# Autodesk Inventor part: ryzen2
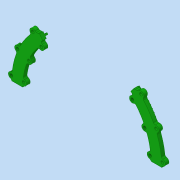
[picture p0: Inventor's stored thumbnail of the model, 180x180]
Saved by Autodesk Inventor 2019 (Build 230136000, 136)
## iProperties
Created: 2022-03
Part Number: ryzen2
Material: Типовые
Document SubType Name: Modeling
Designer: mitof
Density: 1 g/cm^3
Appearance: Темно-зеленый
Author: mitof
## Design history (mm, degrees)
sketch "Эскиз1"
  geometry: L1 (-74.2, 0)-(-71, 0); L2 (-83, 0)-(-79.8, 0); L3 (57.032, 53.211)-(58.347, 54.439); L4 (55.732, 60)-(53.666, 60); L5 (-53.666, 60)-(-55.732, 60); L6 (79.8, 0)-(83, 0); L7 (71, 0)-(74.2, 0); L8 (-58.347, 54.439)-(-57.032, 53.211); L9 (-55.57, 51.846)-(-54.254, 50.617); L10 (54.254, 50.617)-(55.57, 51.846); L11 (-79.8, 0)-(-74.2, 0); L12 (74.2, 0)-(79.8, 0); C1 r 1.35 at (0, 81); C2 r 1.35 at (-83.5, 5); C3 r 1.35 at (-70, 5); C4 r 1.35 at (76.568, 33.925); C5 r 1.35 at (64.068, 28.64); C6 r 1.35 at (0, 73); C7 r 1.35 at (83.5, 5); C8 r 1.35 at (70, 5); C9 r 1.35 at (59.809, 58.536); C10 r 1.35 at (-59.809, 58.536); C11 r 1.35 at (-50.409, 48.825); C12 r 1.35 at (50.409, 48.825); C13 r 1.35 at (-76.568, 33.925); C14 r 1.35 at (-64.068, 28.64); A1 r 2 centre (-5.285, 81.829) between (-5.156, 79.834) and (-3.309, 81.519); A2 r 2 centre (5.285, 81.829) between (3.309, 81.519) and (5.156, 79.834); A3 r 3.35 centre (0, 81) between (3.309, 81.519) and (-3.309, 81.519); A4 r 2 centre (-84.376, 10.278) between (-84.049, 8.305) and (-82.391, 10.036); A5 r 3.35 centre (-83.5, 5) between (-84.049, 8.305) and (-84.436, 1.784); A6 r 2 centre (-68.263, 10.06) between (-70.241, 10.352) and (-68.912, 8.168); A7 r 3.35 centre (-70, 5) between (-69.384, 1.707) and (-68.912, 8.168); A8 r 2 centre (-69.017, -0.259) between (-69.384, 1.707) and (-71, 0); A9 r 2 centre (-84.995, -0.137) between (-83, 0) and (-84.436, 1.784); A10 r 79.8 centre (0, 0) between (79.8, 0) and (58.347, 54.439); A11 r 71 centre (0, 0) between (70.241, 10.352) and (66.808, 24.036); A12 r 83 centre (0, 0) between (82.391, 10.036) and (77.812, 28.883); A13 r 74.2 centre (0, 0) between (74.2, 0) and (54.254, 50.617); A14 r 2 centre (64.926, 23.359) between (66.808, 24.036) and (64.605, 25.333); A15 r 2 centre (79.687, 29.579) between (78.521, 31.204) and (77.812, 28.883); A16 r 3.35 centre (76.568, 33.925) between (78.521, 31.204) and (75.864, 37.201); A17 r 3.35 centre (64.068, 28.64) between (61.962, 31.245) and (64.605, 25.333); A18 r 2 centre (75.444, 39.156) between (73.669, 38.235) and (75.864, 37.201); A19 r 83 centre (0, 0) between (73.669, 38.235) and (62.774, 54.299); A20 r 2 centre (-5.216, 71.811) between (-3.266, 72.255) and (-5.361, 73.806); A21 r 3.35 centre (0, 73) between (-3.266, 72.255) and (3.266, 72.255); A22 r 80 centre (0, 0) between (52.357, 60.488) and (5.156, 79.834); A23 r 80 centre (0, 0) between (-5.156, 79.834) and (-52.357, 60.488); A24 r 74 centre (0, 0) between (-5.361, 73.806) and (-49.753, 54.778); A25 r 2 centre (53.666, 62) between (52.357, 60.488) and (53.666, 60); A26 r 2 centre (-53.666, 62) between (-53.666, 60) and (-52.357, 60.488); A27 r 78 centre (0, 0) between (57.032, 53.211) and (-57.032, 53.211); A28 r 76 centre (0, 0) between (55.57, 51.846) and (-55.57, 51.846); A29 r 2 centre (84.995, -0.137) between (84.436, 1.784) and (83, 0); A30 r 2 centre (68.263, 10.06) between (68.912, 8.168) and (70.241, 10.352); A31 r 3.35 centre (70, 5) between (68.912, 8.168) and (69.384, 1.707); A32 r 2 centre (84.376, 10.278) between (82.391, 10.036) and (84.049, 8.305); A33 r 2 centre (69.017, -0.259) between (71, 0) and (69.384, 1.707); A34 r 3.35 centre (83.5, 5) between (84.436, 1.784) and (84.049, 8.305); A35 r 2 centre (64.287, 55.608) between (62.613, 56.702) and (62.774, 54.299); A36 r 3.35 centre (59.809, 58.536) between (62.613, 56.702) and (57.256, 60.705); A37 r 2 centre (55.732, 62) between (55.732, 60) and (57.256, 60.705); A38 r 2 centre (-55.732, 62) between (-57.256, 60.705) and (-55.732, 60); A39 r 3.35 centre (-59.809, 58.536) between (-57.256, 60.705) and (-62.613, 56.702); A40 r 2 centre (-64.287, 55.608) between (-62.774, 54.299) and (-62.613, 56.702); A41 r 2 centre (-48.408, 53.298) between (-49.753, 54.778) and (-50.393, 53.542); A42 r 2 centre (-48.408, 53.787) between (-50.393, 53.542) and (-49.156, 51.932); A43 r 3.35 centre (-50.409, 48.825) between (-52.045, 45.902) and (-49.156, 51.932); A44 r 2 centre (-53.021, 44.156) between (-52.045, 45.902) and (-54.558, 45.436); A45 r 2 centre (60.705, 32.801) between (61.962, 31.245) and (62.465, 33.751); A46 r 71 centre (0, 0) between (62.465, 33.751) and (54.558, 45.436); A47 r 2 centre (53.021, 44.156) between (54.558, 45.436) and (52.045, 45.902); A48 r 3.35 centre (50.409, 48.825) between (49.156, 51.932) and (52.045, 45.902); A49 r 2 centre (48.408, 53.787) between (49.156, 51.932) and (50.393, 53.542); A50 r 2 centre (48.408, 53.298) between (50.393, 53.542) and (49.753, 54.778); A51 r 74 centre (0, 0) between (49.753, 54.778) and (5.361, 73.806); A52 r 2 centre (5.216, 71.811) between (5.361, 73.806) and (3.266, 72.255); A53 r 83 centre (0, 0) between (-62.774, 54.299) and (-73.669, 38.235); A54 r 2 centre (-75.444, 39.156) between (-75.864, 37.201) and (-73.669, 38.235); A55 r 3.35 centre (-76.568, 33.925) between (-75.864, 37.201) and (-78.521, 31.204); A56 r 2 centre (-79.687, 29.579) between (-77.812, 28.883) and (-78.521, 31.204); A57 r 83 centre (0, 0) between (-77.812, 28.883) and (-82.391, 10.036); A58 r 71 centre (0, 0) between (-66.808, 24.036) and (-70.241, 10.352); A59 r 79.8 centre (0, 0) between (-58.347, 54.439) and (-79.8, 0); A60 r 74.2 centre (0, 0) between (-54.254, 50.617) and (-74.2, 0); A61 r 3.35 centre (-64.068, 28.64) between (-64.605, 25.333) and (-61.962, 31.245); A62 r 2 centre (-60.705, 32.801) between (-62.465, 33.751) and (-61.962, 31.245); A63 r 71 centre (0, 0) between (-54.558, 45.436) and (-62.465, 33.751); A64 r 2 centre (-64.926, 23.359) between (-64.605, 25.333) and (-66.808, 24.036); 2 further points
  constraints: 128 point on circle, 78 centre point, 24 end point, 2 collinear
extrude "Выдавливание1" new body sketch "Эскиз1" distance "d0" = 4; taper "d1" = 0 deg
sketch "Эскиз2"
  geometry: L1 (58.347, 54.439)-(57.032, 53.211) reference; L2 (55.57, 51.846)-(54.254, 50.617) reference; L3 (-57.032, 53.211)-(-58.347, 54.439) reference; L4 (-54.254, 50.617)-(-55.57, 51.846) reference; L5 (-54.537, 50.607)-(-55.852, 51.836); L6 (55.852, 51.836)-(54.537, 50.607); L7 (-58.337, 54.156)-(-57.022, 52.928); L8 (57.022, 52.928)-(58.337, 54.156); L9 (79.6, 0)-(74.4, 0); L10 (83, 0)-(71, 0) reference; L11 (-74.4, 0)-(-79.6, 0); L12 (-71, 0)-(-83, 0) reference; A1 r 74.2 centre (0, 0) between (74.2, 0) and (54.254, 50.617) reference; A2 r 79.8 centre (0, 0) between (79.8, 0) and (58.347, 54.439) reference; A3 r 78 centre (0, 0) between (57.032, 53.211) and (-57.032, 53.211) reference; A4 r 76 centre (0, 0) between (55.57, 51.846) and (-55.57, 51.846) reference; A5 r 74.2 centre (0, 0) between (-54.254, 50.617) and (-74.2, 0) reference; A6 r 79.8 centre (0, 0) between (-58.347, 54.439) and (-79.8, 0) reference; A7 r 74.4 centre (0, 0) between (-54.537, 50.607) and (-74.4, 0); A8 r 76.2 centre (0, 0) between (55.852, 51.836) and (-55.852, 51.836); A9 r 74.4 centre (0, 0) between (74.4, 0) and (54.537, 50.607); A10 r 79.6 centre (0, 0) between (-58.337, 54.156) and (-79.6, 0); A11 r 77.8 centre (0, 0) between (57.022, 52.928) and (-57.022, 52.928); A12 r 79.6 centre (0, 0) between (79.6, 0) and (58.337, 54.156); 1 further point
  constraints: 12 end point, 12 point on circle, 6 centre point, 1 collinear, 8 other
  dimensions: "d2" = 0.2 radial gap between concentric circles of A5 A7; "d3" = 0.2 radial gap between concentric circles of A6 A10
extrude "Выдавливание2" join sketch "Эскиз2" distance "d4" = 3; taper "d5" = 0 deg
sketch "Эскиз3"
  geometry: L1 (71, 0)-(83, 0) reference; L2 (55.732, 60)-(53.666, 60) reference; L3 (-53.666, 60)-(-55.732, 60) reference; L4 (-83, 0)-(-71, 0) reference; C1 r 1.35 at (-83.5, 5) reference; C2 r 1.6 at (-83.5, 5); C3 r 1.35 at (-76.568, 33.925) reference; C4 r 1.35 at (-59.809, 58.536) reference; C5 r 1.35 at (59.809, 58.536) reference; C6 r 1.35 at (83.5, 5) reference; C7 r 1.35 at (76.568, 33.925) reference; C8 r 1.35 at (-83.5, 5) reference; C9 r 1.35 at (0, 81) reference; C10 r 1.35 at (-64.068, 28.64) reference; C11 r 1.35 at (50.409, 48.825) reference; C12 r 1.35 at (-50.409, 48.825) reference; C13 r 1.35 at (70, 5) reference; C14 r 1.35 at (0, 73) reference; C15 r 1.35 at (64.068, 28.64) reference; C16 r 1.35 at (-70, 5) reference; C17 r 1.6 at (-70, 5); C18 r 1.6 at (-76.568, 33.925); C19 r 1.6 at (-64.068, 28.64); C20 r 1.6 at (-59.809, 58.536); C21 r 1.6 at (-50.409, 48.825); C22 r 1.6 at (0, 73); C23 r 1.35 at (0, 81) reference; C24 r 1.6 at (0, 81); C25 r 1.6 at (50.409, 48.825); C26 r 1.6 at (59.809, 58.536); C27 r 1.6 at (64.068, 28.64); C28 r 1.6 at (76.568, 33.925); C29 r 1.6 at (70, 5); C30 r 1.6 at (83.5, 5); A1 r 71 centre (0, 0) between (-66.808, 24.036) and (-70.241, 10.352) reference; A2 r 2 centre (-64.926, 23.359) between (-64.605, 25.333) and (-66.808, 24.036) reference; A3 r 3.35 centre (-64.068, 28.64) between (-64.605, 25.333) and (-61.962, 31.245) reference; A4 r 2 centre (-60.705, 32.801) between (-62.465, 33.751) and (-61.962, 31.245) reference; A5 r 71 centre (0, 0) between (-54.558, 45.436) and (-62.465, 33.751) reference; A6 r 2 centre (-53.021, 44.156) between (-52.045, 45.902) and (-54.558, 45.436) reference; A7 r 3.35 centre (-50.409, 48.825) between (-52.045, 45.902) and (-49.156, 51.932) reference; A8 r 2 centre (-48.408, 53.787) between (-50.393, 53.542) and (-49.156, 51.932) reference; A9 r 2 centre (-48.408, 53.298) between (-49.753, 54.778) and (-50.393, 53.542) reference; A10 r 74 centre (0, 0) between (-5.361, 73.806) and (-49.753, 54.778) reference; A11 r 2 centre (-5.216, 71.811) between (-3.266, 72.255) and (-5.361, 73.806) reference; A12 r 3.35 centre (0, 73) between (-3.266, 72.255) and (3.266, 72.255) reference; A13 r 2 centre (5.216, 71.811) between (5.361, 73.806) and (3.266, 72.255) reference; A14 r 74 centre (0, 0) between (49.753, 54.778) and (5.361, 73.806) reference; A15 r 2 centre (48.408, 53.298) between (50.393, 53.542) and (49.753, 54.778) reference; A16 r 2 centre (48.408, 53.787) between (49.156, 51.932) and (50.393, 53.542) reference; A17 r 3.35 centre (50.409, 48.825) between (49.156, 51.932) and (52.045, 45.902) reference; A18 r 2 centre (53.021, 44.156) between (54.558, 45.436) and (52.045, 45.902) reference; A19 r 71 centre (0, 0) between (62.465, 33.751) and (54.558, 45.436) reference; A20 r 2 centre (60.705, 32.801) between (61.962, 31.245) and (62.465, 33.751) reference; A21 r 3.35 centre (64.068, 28.64) between (61.962, 31.245) and (64.605, 25.333) reference; A22 r 2 centre (64.926, 23.359) between (66.808, 24.036) and (64.605, 25.333) reference; A23 r 71 centre (0, 0) between (70.241, 10.352) and (66.808, 24.036) reference; A24 r 2 centre (68.263, 10.06) between (68.912, 8.168) and (70.241, 10.352) reference; A25 r 3.35 centre (70, 5) between (68.912, 8.168) and (69.384, 1.707) reference; A26 r 2 centre (69.017, -0.259) between (71, 0) and (69.384, 1.707) reference; A27 r 2 centre (84.995, -0.137) between (84.436, 1.784) and (83, 0) reference; A28 r 3.35 centre (83.5, 5) between (84.436, 1.784) and (84.049, 8.305) reference; A29 r 2 centre (84.376, 10.278) between (82.391, 10.036) and (84.049, 8.305) reference; A30 r 83 centre (0, 0) between (82.391, 10.036) and (77.812, 28.883) reference; A31 r 2 centre (79.687, 29.579) between (78.521, 31.204) and (77.812, 28.883) reference; A32 r 3.35 centre (76.568, 33.925) between (78.521, 31.204) and (75.864, 37.201) reference; A33 r 2 centre (75.444, 39.156) between (73.669, 38.235) and (75.864, 37.201) reference; A34 r 83 centre (0, 0) between (73.669, 38.235) and (62.774, 54.299) reference; A35 r 2 centre (64.287, 55.608) between (62.613, 56.702) and (62.774, 54.299) reference; A36 r 3.35 centre (59.809, 58.536) between (62.613, 56.702) and (57.256, 60.705) reference; A37 r 2 centre (55.732, 62) between (55.732, 60) and (57.256, 60.705) reference; A38 r 2 centre (53.666, 62) between (52.357, 60.488) and (53.666, 60) reference; A39 r 80 centre (0, 0) between (52.357, 60.488) and (5.156, 79.834) reference; A40 r 2 centre (5.285, 81.829) between (3.309, 81.519) and (5.156, 79.834) reference; A41 r 3.35 centre (0, 81) between (3.309, 81.519) and (-3.309, 81.519) reference; A42 r 2 centre (-5.285, 81.829) between (-5.156, 79.834) and (-3.309, 81.519) reference; A43 r 80 centre (0, 0) between (-5.156, 79.834) and (-52.357, 60.488) reference; A44 r 2 centre (-53.666, 62) between (-53.666, 60) and (-52.357, 60.488) reference; A45 r 2 centre (-55.732, 62) between (-57.256, 60.705) and (-55.732, 60) reference; A46 r 3.35 centre (-59.809, 58.536) between (-57.256, 60.705) and (-62.613, 56.702) reference; A47 r 2 centre (-64.287, 55.608) between (-62.774, 54.299) and (-62.613, 56.702) reference; A48 r 83 centre (0, 0) between (-62.774, 54.299) and (-73.669, 38.235) reference; A49 r 2 centre (-75.444, 39.156) between (-75.864, 37.201) and (-73.669, 38.235) reference; A50 r 3.35 centre (-76.568, 33.925) between (-75.864, 37.201) and (-78.521, 31.204) reference; A51 r 2 centre (-79.687, 29.579) between (-77.812, 28.883) and (-78.521, 31.204) reference; A52 r 83 centre (0, 0) between (-77.812, 28.883) and (-82.391, 10.036) reference; A53 r 2 centre (-84.376, 10.278) between (-84.049, 8.305) and (-82.391, 10.036) reference; A54 r 3.35 centre (-83.5, 5) between (-84.049, 8.305) and (-84.436, 1.784) reference; A55 r 2 centre (-84.995, -0.137) between (-83, 0) and (-84.436, 1.784) reference; A56 r 2 centre (-69.017, -0.259) between (-69.384, 1.707) and (-71, 0) reference; A57 r 3.35 centre (-70, 5) between (-69.384, 1.707) and (-68.912, 8.168) reference; A58 r 2 centre (-68.263, 10.06) between (-70.241, 10.352) and (-68.912, 8.168) reference; A59 r 3.35 centre (0, 73) between (-3.266, 72.255) and (3.266, 72.255) reference; 1 further point
  constraints: 14 centre point, 14 coincident
  dimensions: "d6" = 3.2 diameter of C2; "d7" = 3.2 diameter of C17; "d8" = 3.2 diameter of C18; "d9" = 3.2 diameter of C19; "d10" = 3.2 diameter of C20; "d11" = 3.2 diameter of C21; "d12" = 3.2 diameter of C22; "d13" = 3.2 diameter of C24; "d14" = 3.2 diameter of C25; "d15" = 3.2 diameter of C26; "d16" = 3.2 diameter of C27; "d17" = 3.2 diameter of C28; "d18" = 3.2 diameter of C29; "d19" = 3.2 diameter of C30
extrude "Выдавливание3" cut sketch "Эскиз3" extent not by distance; stored distance "d20" = 2.2; taper "d21" = 0 deg
sketch "Эскиз4"
  geometry: L1 (-54.537, 50.607)-(-55.852, 51.836) reference; L2 (55.852, 51.836)-(54.537, 50.607) reference; L3 (74.4, 0)-(79.6, 0) reference; L4 (58.337, 54.156)-(57.022, 52.928) reference; L5 (-57.022, 52.928)-(-58.337, 54.156) reference; L6 (-79.6, 0)-(-74.4, 0) reference; L7 (56.089, 48.881)-(60.009, 52.297); L8 (57.761, 46.894)-(61.798, 50.171); A1 r 74.4 centre (0, 0) between (-54.537, 50.607) and (-74.4, 0) reference; A2 r 76.2 centre (0, 0) between (55.852, 51.836) and (-55.852, 51.836) reference; A3 r 74.4 centre (0, 0) between (74.4, 0) and (54.537, 50.607) reference; A4 r 79.6 centre (0, 0) between (79.6, 0) and (58.337, 54.156) reference; A5 r 77.8 centre (0, 0) between (57.022, 52.928) and (-57.022, 52.928) reference; A6 r 79.6 centre (0, 0) between (-58.337, 54.156) and (-79.6, 0) reference; A7 r 79.6 centre (0, 0) between (79.6, 0) and (58.337, 54.156) reference; 1 further point
  constraints: 4 end point, 4 point on circle
  dimensions: "d26" = 2 deg angle of L7 L8
extrude "Выдавливание4" cut sketch "Эскиз4" distance "d27" = 1.2; taper "d28" = 0 deg
fillet "Сопряжение1" dims "d29" = 1.2
pattern_circular "Круговой массив1" dims angle "d31" = 37 deg
mirror "Зеркальное отражение1"
sketch "Эскиз5"
  geometry: L1 (54.537, 50.607)-(55.852, 51.836) reference; L2 (-55.852, 51.836)-(-54.537, 50.607) reference; L3 (-71, 0)-(-74.4, 0) reference; L4 (74.4, 0)-(71, 0) reference; L5 (83, 0)-(79.6, 0) reference; L6 (53.666, 60)-(55.732, 60) reference; L7 (-55.732, 60)-(-53.666, 60) reference; L8 (-79.6, 0)-(-83, 0) reference; L9 (-58.337, 54.156)-(-57.022, 52.928) reference; L10 (57.022, 52.928)-(58.337, 54.156) reference; L11 (-55.1, 50.586)-(-56.416, 51.815); L12 (56.416, 51.815)-(55.1, 50.586); L13 (74.799, -0.4)-(70.611, -0.4); L14 (-70.611, -0.4)-(-74.799, -0.4); L15 (-79.199, -0.4)-(-83.417, -0.4); L16 (-55.732, 60.4)-(-53.666, 60.4); L17 (53.666, 60.4)-(55.732, 60.4); L18 (83.417, -0.4)-(79.199, -0.4); L19 (58.316, 53.59)-(57.001, 52.361); L20 (-57.001, 52.361)-(-58.316, 53.59); L21 (-58.316, 53.59)-(-58.045, 53.883); L22 (-57.022, 52.928)-(-58.337, 54.156) reference; L23 (-55.1, 50.586)-(-54.827, 50.879); L24 (-74.8, 0)-(-74.4, 0); L25 (-71, 0)-(-83, 0) reference; L26 (-79.2, 0)-(-79.6, 0); C1 r 1.6 at (-70, 5) reference; C2 r 1.6 at (-64.068, 28.64) reference; C3 r 1.6 at (-50.409, 48.825) reference; C4 r 1.6 at (0, 73) reference; C5 r 1.6 at (70, 5) reference; C6 r 1.6 at (64.068, 28.64) reference; C7 r 1.6 at (50.409, 48.825) reference; C8 r 1.6 at (59.809, 58.536) reference; C9 r 1.6 at (76.568, 33.925) reference; C10 r 1.6 at (83.5, 5) reference; C11 r 1.6 at (0, 81) reference; C12 r 1.6 at (-59.809, 58.536) reference; C13 r 1.6 at (-76.568, 33.925) reference; C14 r 1.6 at (-83.5, 5) reference; A1 r 74.4 centre (0, 0) between (74.4, 0) and (54.537, 50.607) reference; A2 r 76.2 centre (0, 0) between (55.852, 51.836) and (-55.852, 51.836) reference; A3 r 74.4 centre (0, 0) between (-54.537, 50.607) and (-74.4, 0) reference; A4 r 2 centre (-69.017, -0.259) between (-69.384, 1.707) and (-71, 0) reference; A5 r 3.35 centre (-70, 5) between (-69.384, 1.707) and (-68.912, 8.168) reference; A6 r 2 centre (-68.263, 10.06) between (-70.241, 10.352) and (-68.912, 8.168) reference; A7 r 71 centre (0, 0) between (-66.808, 24.036) and (-70.241, 10.352) reference; A8 r 2 centre (-64.926, 23.359) between (-64.605, 25.333) and (-66.808, 24.036) reference; A9 r 3.35 centre (-64.068, 28.64) between (-64.605, 25.333) and (-61.962, 31.245) reference; A10 r 2 centre (-60.705, 32.801) between (-62.465, 33.751) and (-61.962, 31.245) reference; A11 r 71 centre (0, 0) between (-54.558, 45.436) and (-62.465, 33.751) reference; A12 r 2 centre (-53.021, 44.156) between (-52.045, 45.902) and (-54.558, 45.436) reference; A13 r 3.35 centre (-50.409, 48.825) between (-52.045, 45.902) and (-49.156, 51.932) reference; A14 r 2 centre (-48.408, 53.787) between (-50.393, 53.542) and (-49.156, 51.932) reference; A15 r 2 centre (-48.408, 53.298) between (-49.753, 54.778) and (-50.393, 53.542) reference; A16 r 74 centre (0, 0) between (-5.361, 73.806) and (-49.753, 54.778) reference; A17 r 2 centre (-5.216, 71.811) between (-3.266, 72.255) and (-5.361, 73.806) reference; A18 r 3.35 centre (0, 73) between (-3.266, 72.255) and (3.266, 72.255) reference; A19 r 2 centre (5.216, 71.811) between (5.361, 73.806) and (3.266, 72.255) reference; A20 r 74 centre (0, 0) between (49.753, 54.778) and (5.361, 73.806) reference; A21 r 2 centre (48.408, 53.298) between (50.393, 53.542) and (49.753, 54.778) reference; A22 r 2 centre (48.408, 53.787) between (49.156, 51.932) and (50.393, 53.542) reference; A23 r 3.35 centre (50.409, 48.825) between (49.156, 51.932) and (52.045, 45.902) reference; A24 r 2 centre (53.021, 44.156) between (54.558, 45.436) and (52.045, 45.902) reference; A25 r 71 centre (0, 0) between (62.465, 33.751) and (54.558, 45.436) reference; A26 r 2 centre (60.705, 32.801) between (61.962, 31.245) and (62.465, 33.751) reference; A27 r 3.35 centre (64.068, 28.64) between (61.962, 31.245) and (64.605, 25.333) reference; A28 r 2 centre (64.926, 23.359) between (66.808, 24.036) and (64.605, 25.333) reference; A29 r 71 centre (0, 0) between (70.241, 10.352) and (66.808, 24.036) reference; A30 r 2 centre (68.263, 10.06) between (68.912, 8.168) and (70.241, 10.352) reference; A31 r 3.35 centre (70, 5) between (68.912, 8.168) and (69.384, 1.707) reference; A32 r 2 centre (69.017, -0.259) between (71, 0) and (69.384, 1.707) reference; A33 r 79.6 centre (0, 0) between (79.6, 0) and (58.337, 54.156) reference; A34 r 2 centre (84.995, -0.137) between (84.436, 1.784) and (83, 0) reference; A35 r 3.35 centre (83.5, 5) between (84.436, 1.784) and (84.049, 8.305) reference; A36 r 2 centre (84.376, 10.278) between (82.391, 10.036) and (84.049, 8.305) reference; A37 r 83 centre (0, 0) between (82.391, 10.036) and (77.812, 28.883) reference; A38 r 2 centre (79.687, 29.579) between (78.521, 31.204) and (77.812, 28.883) reference; A39 r 3.35 centre (76.568, 33.925) between (78.521, 31.204) and (75.864, 37.201) reference; A40 r 2 centre (75.444, 39.156) between (73.669, 38.235) and (75.864, 37.201) reference; A41 r 83 centre (0, 0) between (73.669, 38.235) and (62.774, 54.299) reference; A42 r 2 centre (64.287, 55.608) between (62.613, 56.702) and (62.774, 54.299) reference; A43 r 3.35 centre (59.809, 58.536) between (62.613, 56.702) and (57.256, 60.705) reference; A44 r 2 centre (55.732, 62) between (55.732, 60) and (57.256, 60.705) reference; A45 r 2 centre (53.666, 62) between (52.357, 60.488) and (53.666, 60) reference; A46 r 80 centre (0, 0) between (52.357, 60.488) and (5.156, 79.834) reference; A47 r 2 centre (5.285, 81.829) between (3.309, 81.519) and (5.156, 79.834) reference; A48 r 3.35 centre (0, 81) between (3.309, 81.519) and (-3.309, 81.519) reference; A49 r 2 centre (-5.285, 81.829) between (-5.156, 79.834) and (-3.309, 81.519) reference; A50 r 80 centre (0, 0) between (-5.156, 79.834) and (-52.357, 60.488) reference; A51 r 2 centre (-53.666, 62) between (-53.666, 60) and (-52.357, 60.488) reference; A52 r 2 centre (-55.732, 62) between (-57.256, 60.705) and (-55.732, 60) reference; A53 r 3.35 centre (-59.809, 58.536) between (-57.256, 60.705) and (-62.613, 56.702) reference; A54 r 2 centre (-64.287, 55.608) between (-62.774, 54.299) and (-62.613, 56.702) reference; A55 r 83 centre (0, 0) between (-62.774, 54.299) and (-73.669, 38.235) reference; A56 r 2 centre (-75.444, 39.156) between (-75.864, 37.201) and (-73.669, 38.235) reference; A57 r 3.35 centre (-76.568, 33.925) between (-75.864, 37.201) and (-78.521, 31.204) reference; A58 r 2 centre (-79.687, 29.579) between (-77.812, 28.883) and (-78.521, 31.204) reference; A59 r 83 centre (0, 0) between (-77.812, 28.883) and (-82.391, 10.036) reference; A60 r 2 centre (-84.376, 10.278) between (-84.049, 8.305) and (-82.391, 10.036) reference; A61 r 3.35 centre (-83.5, 5) between (-84.049, 8.305) and (-84.436, 1.784) reference; A62 r 2 centre (-84.995, -0.137) between (-83, 0) and (-84.436, 1.784) reference; A63 r 79.6 centre (0, 0) between (-58.337, 54.156) and (-79.6, 0) reference; A64 r 77.8 centre (0, 0) between (57.022, 52.928) and (-57.022, 52.928) reference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; 1 further point
  constraints: 130 point on circle, 64 centre point, 28 end point, 3 point on line, 2 collinear, 1 perpendicular, 72 other
  dimensions: "d33" = 0.4 radial gap between concentric circles of A3 A65; "d34" = 0.4 radial gap between concentric circles of A63 A128
extrude "Выдавливание5" cut sketch "Эскиз5" stored distance "d35" = 10; taper "d36" = 0 deg
sketch "Эскиз6"
  geometry: L1 (83, 0)-(79.6, 0) reference; L2 (53.666, 60)-(55.732, 60) reference; L3 (-55.732, 60)-(-53.666, 60) reference; L4 (-79.2, 0)-(-83, 0) reference; L5 (-58.316, 53.59)-(-58.045, 53.883) reference; L6 (-58.045, 53.883)-(-57.022, 52.928) reference; L7 (57.022, 52.928)-(58.337, 54.156) reference; L8 (54.537, 50.607)-(55.852, 51.836) reference; L9 (-55.852, 51.836)-(-54.827, 50.879) reference; L10 (-54.827, 50.879)-(-55.1, 50.586) reference; L11 (-71, 0)-(-74.8, 0) reference; L12 (74.4, 0)-(71, 0) reference; L13 (79.199, -0.4)-(83.417, -0.4); L14 (55.732, 60.4)-(53.666, 60.4); L15 (-53.666, 60.4)-(-55.732, 60.4); L16 (-83.417, -0.4)-(-78.799, -0.4); L17 (-58.024, 53.317)-(-57.001, 52.361); L18 (57.001, 52.361)-(58.316, 53.59); L19 (74.799, -0.4)-(70.611, -0.4); L20 (-70.611, -0.4)-(-75.199, -0.4); L21 (-55.394, 50.858)-(-55.393, 50.859); L22 (-55.393, 50.859)-(-56.416, 51.815); L23 (56.416, 51.815)-(55.1, 50.586); L24 (58.316, 53.59)-(58.043, 53.882); L25 (55.1, 50.586)-(54.827, 50.879); L26 (83, 0)-(71, 0) reference; L27 (79.2, 0)-(79.6, 0); L28 (74.8, 0)-(74.4, 0); C1 r 1.6 at (59.809, 58.536) reference; C2 r 1.6 at (76.568, 33.925) reference; C3 r 1.6 at (83.5, 5) reference; C4 r 1.6 at (0, 81) reference; C5 r 1.6 at (-59.809, 58.536) reference; C6 r 1.6 at (-76.568, 33.925) reference; C7 r 1.6 at (-83.5, 5) reference; C8 r 1.6 at (-70, 5) reference; C9 r 1.6 at (-64.068, 28.64) reference; C10 r 1.6 at (-50.409, 48.825) reference; C11 r 1.6 at (0, 73) reference; C12 r 1.6 at (70, 5) reference; C13 r 1.6 at (64.068, 28.64) reference; C14 r 1.6 at (50.409, 48.825) reference; A1 r 79.6 centre (0, 0) between (79.6, 0) and (58.337, 54.156) reference; A2 r 2 centre (84.995, -0.137) between (84.436, 1.784) and (83, 0) reference; A3 r 3.35 centre (83.5, 5) between (84.436, 1.784) and (84.049, 8.305) reference; A4 r 2 centre (84.376, 10.278) between (82.391, 10.036) and (84.049, 8.305) reference; A5 r 83 centre (0, 0) between (82.391, 10.036) and (77.812, 28.883) reference; A6 r 2 centre (79.687, 29.579) between (78.521, 31.204) and (77.812, 28.883) reference; A7 r 3.35 centre (76.568, 33.925) between (78.521, 31.204) and (75.864, 37.201) reference; A8 r 2 centre (75.444, 39.156) between (73.669, 38.235) and (75.864, 37.201) reference; A9 r 83 centre (0, 0) between (73.669, 38.235) and (62.774, 54.299) reference; A10 r 2 centre (64.287, 55.608) between (62.613, 56.702) and (62.774, 54.299) reference; A11 r 3.35 centre (59.809, 58.536) between (62.613, 56.702) and (57.256, 60.705) reference; A12 r 2 centre (55.732, 62) between (55.732, 60) and (57.256, 60.705) reference; A13 r 2 centre (53.666, 62) between (52.357, 60.488) and (53.666, 60) reference; A14 r 80 centre (0, 0) between (52.357, 60.488) and (5.156, 79.834) reference; A15 r 2 centre (5.285, 81.829) between (3.309, 81.519) and (5.156, 79.834) reference; A16 r 3.35 centre (0, 81) between (3.309, 81.519) and (-3.309, 81.519) reference; A17 r 2 centre (-5.285, 81.829) between (-5.156, 79.834) and (-3.309, 81.519) reference; A18 r 80 centre (0, 0) between (-5.156, 79.834) and (-52.357, 60.488) reference; A19 r 2 centre (-53.666, 62) between (-53.666, 60) and (-52.357, 60.488) reference; A20 r 2 centre (-55.732, 62) between (-57.256, 60.705) and (-55.732, 60) reference; A21 r 3.35 centre (-59.809, 58.536) between (-57.256, 60.705) and (-62.613, 56.702) reference; A22 r 2 centre (-64.287, 55.608) between (-62.774, 54.299) and (-62.613, 56.702) reference; A23 r 83 centre (0, 0) between (-62.774, 54.299) and (-73.669, 38.235) reference; A24 r 2 centre (-75.444, 39.156) between (-75.864, 37.201) and (-73.669, 38.235) reference; A25 r 3.35 centre (-76.568, 33.925) between (-75.864, 37.201) and (-78.521, 31.204) reference; A26 r 2 centre (-79.687, 29.579) between (-77.812, 28.883) and (-78.521, 31.204) reference; A27 r 83 centre (0, 0) between (-77.812, 28.883) and (-82.391, 10.036) reference; A28 r 2 centre (-84.376, 10.278) between (-84.049, 8.305) and (-82.391, 10.036) reference; A29 r 3.35 centre (-83.5, 5) between (-84.049, 8.305) and (-84.436, 1.784) reference; A30 r 2 centre (-84.995, -0.137) between (-83, 0) and (-84.436, 1.784) reference; A31 r 79.2 centre (0, 0) between (-58.316, 53.59) and (-79.2, 0) reference; A32 r 77.8 centre (0, 0) between (57.022, 52.928) and (-57.022, 52.928) reference; A33 r 74.4 centre (0, 0) between (74.4, 0) and (54.537, 50.607) reference; A34 r 76.2 centre (0, 0) between (55.852, 51.836) and (-55.852, 51.836) reference; A35 r 74.8 centre (0, 0) between (-55.1, 50.586) and (-74.8, 0) reference; A36 r 2 centre (-69.017, -0.259) between (-69.384, 1.707) and (-71, 0) reference; A37 r 3.35 centre (-70, 5) between (-69.384, 1.707) and (-68.912, 8.168) reference; A38 r 2 centre (-68.263, 10.06) between (-70.241, 10.352) and (-68.912, 8.168) reference; A39 r 71 centre (0, 0) between (-66.808, 24.036) and (-70.241, 10.352) reference; A40 r 2 centre (-64.926, 23.359) between (-64.605, 25.333) and (-66.808, 24.036) reference; A41 r 3.35 centre (-64.068, 28.64) between (-64.605, 25.333) and (-61.962, 31.245) reference; A42 r 2 centre (-60.705, 32.801) between (-62.465, 33.751) and (-61.962, 31.245) reference; A43 r 71 centre (0, 0) between (-54.558, 45.436) and (-62.465, 33.751) reference; A44 r 2 centre (-53.021, 44.156) between (-52.045, 45.902) and (-54.558, 45.436) reference; A45 r 3.35 centre (-50.409, 48.825) between (-52.045, 45.902) and (-49.156, 51.932) reference; A46 r 2 centre (-48.408, 53.787) between (-50.393, 53.542) and (-49.156, 51.932) reference; A47 r 2 centre (-48.408, 53.298) between (-49.753, 54.778) and (-50.393, 53.542) reference; A48 r 74 centre (0, 0) between (-5.361, 73.806) and (-49.753, 54.778) reference; A49 r 2 centre (-5.216, 71.811) between (-3.266, 72.255) and (-5.361, 73.806) reference; A50 r 3.35 centre (0, 73) between (-3.266, 72.255) and (3.266, 72.255) reference; A51 r 2 centre (5.216, 71.811) between (5.361, 73.806) and (3.266, 72.255) reference; A52 r 74 centre (0, 0) between (49.753, 54.778) and (5.361, 73.806) reference; A53 r 2 centre (48.408, 53.298) between (50.393, 53.542) and (49.753, 54.778) reference; A54 r 2 centre (48.408, 53.787) between (49.156, 51.932) and (50.393, 53.542) reference; A55 r 3.35 centre (50.409, 48.825) between (49.156, 51.932) and (52.045, 45.902) reference; A56 r 2 centre (53.021, 44.156) between (54.558, 45.436) and (52.045, 45.902) reference; A57 r 71 centre (0, 0) between (62.465, 33.751) and (54.558, 45.436) reference; A58 r 2 centre (60.705, 32.801) between (61.962, 31.245) and (62.465, 33.751) reference; A59 r 3.35 centre (64.068, 28.64) between (61.962, 31.245) and (64.605, 25.333) reference; A60 r 2 centre (64.926, 23.359) between (66.808, 24.036) and (64.605, 25.333) reference; A61 r 71 centre (0, 0) between (70.241, 10.352) and (66.808, 24.036) reference; A62 r 2 centre (68.263, 10.06) between (68.912, 8.168) and (70.241, 10.352) reference; A63 r 3.35 centre (70, 5) between (68.912, 8.168) and (69.384, 1.707) reference; A64 r 2 centre (69.017, -0.259) between (71, 0) and (69.384, 1.707) reference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; 1 further point
  constraints: 130 point on circle, 64 centre point, 30 end point, 4 point on line, 2 collinear, 2 perpendicular, 73 other
  dimensions: "d37" = 0.4 radial gap between concentric circles of A1 A65; "d38" = 0.4 radial gap between concentric circles of A33 A97
extrude "Выдавливание6" cut sketch "Эскиз6" stored distance "d39" = 10; taper "d40" = 0 deg
sketch "Эскиз8"
  geometry: L1 (71, 0)-(83, 0) reference; L2 (55.732, 60)-(53.666, 60) reference; L3 (-53.666, 60)-(-55.732, 60) reference; L4 (-83, 0)-(-71, 0) reference; L5 (-52.357, 60.488)-(-48.824, 55.608); L6 (52.357, 60.488)-(48.633, 55.774); C1 r 1.6 at (70, 5) reference; C2 r 1.6 at (64.068, 28.64) reference; C3 r 1.6 at (50.409, 48.825) reference; C4 r 1.6 at (0, 73) reference; C5 r 1.6 at (-59.809, 58.536) reference; C6 r 1.6 at (-76.568, 33.925) reference; C7 r 1.6 at (-83.5, 5) reference; C8 r 1.6 at (-70, 5) reference; C9 r 1.6 at (-64.068, 28.64) reference; C10 r 1.6 at (-50.409, 48.825) reference; C11 r 1.6 at (0, 81) reference; C12 r 1.6 at (59.809, 58.536) reference; C13 r 1.6 at (76.568, 33.925) reference; C14 r 1.6 at (83.5, 5) reference; A1 r 77.8 centre (0, 0) between (57.022, 52.928) and (-57.022, 52.928) reference; A2 r 71 centre (0, 0) between (-66.808, 24.036) and (-70.241, 10.352) reference; A3 r 2 centre (-64.926, 23.359) between (-64.605, 25.333) and (-66.808, 24.036) reference; A4 r 3.35 centre (-64.068, 28.64) between (-64.605, 25.333) and (-61.962, 31.245) reference; A5 r 2 centre (-60.705, 32.801) between (-62.465, 33.751) and (-61.962, 31.245) reference; A6 r 71 centre (0, 0) between (-54.558, 45.436) and (-62.465, 33.751) reference; A7 r 2 centre (-53.021, 44.156) between (-52.045, 45.902) and (-54.558, 45.436) reference; A8 r 3.35 centre (-50.409, 48.825) between (-52.045, 45.902) and (-49.156, 51.932) reference; A9 r 2 centre (-48.408, 53.787) between (-50.393, 53.542) and (-49.156, 51.932) reference; A10 r 2 centre (-48.408, 53.298) between (-49.753, 54.778) and (-50.393, 53.542) reference; A11 r 74 centre (0, 0) between (-5.361, 73.806) and (-49.753, 54.778) reference; A12 r 2 centre (-5.216, 71.811) between (-3.266, 72.255) and (-5.361, 73.806) reference; A13 r 3.35 centre (0, 73) between (-3.266, 72.255) and (3.266, 72.255) reference; A14 r 2 centre (5.216, 71.811) between (5.361, 73.806) and (3.266, 72.255) reference; A15 r 74 centre (0, 0) between (49.753, 54.778) and (5.361, 73.806) reference; A16 r 2 centre (48.408, 53.298) between (50.393, 53.542) and (49.753, 54.778) reference; A17 r 2 centre (48.408, 53.787) between (49.156, 51.932) and (50.393, 53.542) reference; A18 r 3.35 centre (50.409, 48.825) between (49.156, 51.932) and (52.045, 45.902) reference; A19 r 2 centre (53.021, 44.156) between (54.558, 45.436) and (52.045, 45.902) reference; A20 r 71 centre (0, 0) between (62.465, 33.751) and (54.558, 45.436) reference; A21 r 2 centre (60.705, 32.801) between (61.962, 31.245) and (62.465, 33.751) reference; A22 r 3.35 centre (64.068, 28.64) between (61.962, 31.245) and (64.605, 25.333) reference; A23 r 2 centre (64.926, 23.359) between (66.808, 24.036) and (64.605, 25.333) reference; A24 r 71 centre (0, 0) between (70.241, 10.352) and (66.808, 24.036) reference; A25 r 2 centre (68.263, 10.06) between (68.912, 8.168) and (70.241, 10.352) reference; A26 r 3.35 centre (70, 5) between (68.912, 8.168) and (69.384, 1.707) reference; A27 r 2 centre (69.017, -0.259) between (71, 0) and (69.384, 1.707) reference; A28 r 2 centre (84.995, -0.137) between (84.436, 1.784) and (83, 0) reference; A29 r 3.35 centre (83.5, 5) between (84.436, 1.784) and (84.049, 8.305) reference; A30 r 2 centre (84.376, 10.278) between (82.391, 10.036) and (84.049, 8.305) reference; A31 r 83 centre (0, 0) between (82.391, 10.036) and (77.812, 28.883) reference; A32 r 2 centre (79.687, 29.579) between (78.521, 31.204) and (77.812, 28.883) reference; A33 r 3.35 centre (76.568, 33.925) between (78.521, 31.204) and (75.864, 37.201) reference; A34 r 2 centre (75.444, 39.156) between (73.669, 38.235) and (75.864, 37.201) reference; A35 r 83 centre (0, 0) between (73.669, 38.235) and (62.774, 54.299) reference; A36 r 2 centre (64.287, 55.608) between (62.613, 56.702) and (62.774, 54.299) reference; A37 r 3.35 centre (59.809, 58.536) between (62.613, 56.702) and (57.256, 60.705) reference; A38 r 2 centre (55.732, 62) between (55.732, 60) and (57.256, 60.705) reference; A39 r 2 centre (53.666, 62) between (52.357, 60.488) and (53.666, 60) reference; A40 r 80 centre (0, 0) between (52.357, 60.488) and (5.156, 79.834) reference; A41 r 2 centre (5.285, 81.829) between (3.309, 81.519) and (5.156, 79.834) reference; A42 r 3.35 centre (0, 81) between (3.309, 81.519) and (-3.309, 81.519) reference; A43 r 2 centre (-5.285, 81.829) between (-5.156, 79.834) and (-3.309, 81.519) reference; A44 r 80 centre (0, 0) between (-5.156, 79.834) and (-52.357, 60.488) reference; A45 r 2 centre (-53.666, 62) between (-53.666, 60) and (-52.357, 60.488) reference; A46 r 2 centre (-55.732, 62) between (-57.256, 60.705) and (-55.732, 60) reference; A47 r 3.35 centre (-59.809, 58.536) between (-57.256, 60.705) and (-62.613, 56.702) reference; A48 r 2 centre (-64.287, 55.608) between (-62.774, 54.299) and (-62.613, 56.702) reference; A49 r 83 centre (0, 0) between (-62.774, 54.299) and (-73.669, 38.235) reference; A50 r 2 centre (-75.444, 39.156) between (-75.864, 37.201) and (-73.669, 38.235) reference; A51 r 3.35 centre (-76.568, 33.925) between (-75.864, 37.201) and (-78.521, 31.204) reference; A52 r 2 centre (-79.687, 29.579) between (-77.812, 28.883) and (-78.521, 31.204) reference; A53 r 83 centre (0, 0) between (-77.812, 28.883) and (-82.391, 10.036) reference; A54 r 2 centre (-84.376, 10.278) between (-84.049, 8.305) and (-82.391, 10.036) reference; A55 r 3.35 centre (-83.5, 5) between (-84.049, 8.305) and (-84.436, 1.784) reference; A56 r 2 centre (-84.995, -0.137) between (-83, 0) and (-84.436, 1.784) reference; A57 r 2 centre (-69.017, -0.259) between (-69.384, 1.707) and (-71, 0) reference; A58 r 3.35 centre (-70, 5) between (-69.384, 1.707) and (-68.912, 8.168) reference; A59 r 2 centre (-68.263, 10.06) between (-70.241, 10.352) and (-68.912, 8.168) reference; A60 r 80 centre (0, 0) between (-5.156, 79.834) and (-52.357, 60.488) reference; A61 r 74 centre (0, 0) between (-5.361, 73.806) and (-49.753, 54.778) reference; A62 r 2 centre (53.666, 62) between (52.357, 60.488) and (53.666, 60) reference; A63 r 74 centre (0, 0) between (49.753, 54.778) and (5.361, 73.806) reference; 1 further point
  constraints: 4 end point, 2 point on circle
extrude "Выдавливание8" cut sketch "Эскиз8" extent not by distance; stored distance "d43" = 0; taper "d44" = 0 deg
node "Твердое тело1"
node "Спроецированная петля1"
node "Спроецированная петля2"
node "Спроецированная петля3"
node "Спроецированная петля4"
node "Спроецированная петля5"
node "Спроецированная петля6"
node "Спроецированная петля8"
